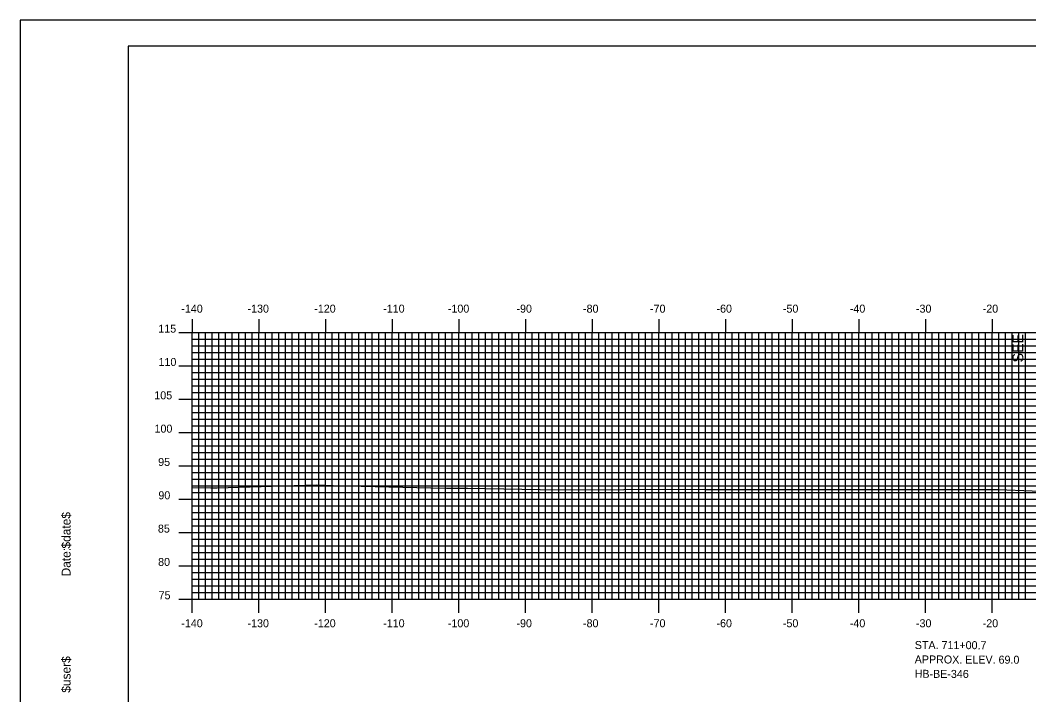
# Model space of a CAD drawing. Extents: x 854903 to 855247, y 364366 to 364586.
# Drawn here: x 854903.5 to 855054.8, y 364484.5 to 364585.7 of the extents above; entities that cross this region are included whole.
import ezdxf

# ---------------------------------------------------------------- set-up
doc = ezdxf.new("R2010")
doc.units = 0
for name, color, linetype in [('ANNOTATION', 7, 'Continuous'), ('BORDER', 7, 'Continuous'), ('BORING - REFUSAL', 7, 'Continuous'), ('H_V ANNOTATION', 7, 'Continuous'), ('MAJOR', 7, 'Continuous'), ('MINOR', 7, 'Continuous'), ('PLOT BOUNDARY', 7, 'Continuous'), ('S_Roadway_Centerline', 7, 'Continuous')]:
    doc.layers.add(name, color=color, linetype=linetype)

msp = doc.modelspace()

# ---------------------------------------------------------------- linework, layer by layer
at = {"layer": 'BORDER'}
msp.add_lwpolyline([(854919.66, 364371.79), (855239.66, 364371.79), (855239.66, 364581.79), (854919.66, 364581.79)], close=True, dxfattribs=at)
at = {"layer": 'MAJOR'}
for p, q in [((854929.26, 364540.79), (854929.26, 364538.79)), ((854939.26, 364540.79), (854939.26, 364538.79)), ((854949.26, 364540.79), (854949.26, 364538.79)), ((854959.26, 364540.79), (854959.26, 364538.79)), ((854969.26, 364540.79), (854969.26, 364538.79)), ((854979.26, 364540.79), (854979.26, 364538.79)), ((854989.26, 364540.79), (854989.26, 364538.79)), ((854999.26, 364540.79), (854999.26, 364538.79)), ((855009.26, 364540.79), (855009.26, 364538.79)), ((855019.26, 364540.79), (855019.26, 364538.79)), ((855029.26, 364540.79), (855029.26, 364538.79)), ((855039.26, 364540.79), (855039.26, 364538.79)), ((855049.26, 364540.79), (855049.26, 364538.79)), ((854927.25, 364538.79), (854929.26, 364538.79)), ((854929.26, 364538.79), (855209.26, 364538.79)), ((854929.26, 364498.79), (854929.26, 364538.79)), ((854929.26, 364498.79), (854929.26, 364538.79)), ((854929.26, 364538.79), (855209.26, 364538.79)), ((854939.26, 364498.79), (854939.26, 364538.79)), ((854949.26, 364498.79), (854949.26, 364538.79)), ((854959.26, 364498.79), (854959.26, 364538.79)), ((854969.26, 364498.79), (854969.26, 364538.79)), ((854979.26, 364498.79), (854979.26, 364538.79)), ((854989.26, 364498.79), (854989.26, 364538.79)), ((854999.26, 364498.79), (854999.26, 364538.79)), ((855009.26, 364498.79), (855009.26, 364538.79)), ((855019.26, 364498.79), (855019.26, 364538.79)), ((855029.26, 364498.79), (855029.26, 364538.79)), ((855039.26, 364498.79), (855039.26, 364538.79)), ((855049.26, 364498.79), (855049.26, 364538.79)), ((854927.25, 364533.79), (854929.26, 364533.79)), ((854929.26, 364533.79), (855209.26, 364533.79)), ((854927.25, 364528.79), (854929.26, 364528.79)), ((854929.26, 364528.79), (855209.26, 364528.79)), ((854927.25, 364523.79), (854929.26, 364523.79)), ((854929.26, 364523.79), (855209.26, 364523.79)), ((854927.25, 364518.79), (854929.26, 364518.79)), ((854929.26, 364518.79), (855209.26, 364518.79)), ((854927.25, 364513.79), (854929.26, 364513.79)), ((854929.26, 364513.79), (855209.26, 364513.79)), ((854927.25, 364508.79), (854929.26, 364508.79)), ((854929.26, 364508.79), (855209.26, 364508.79)), ((854927.25, 364503.79), (854929.26, 364503.79)), ((854929.26, 364503.79), (855209.26, 364503.79)), ((854927.25, 364498.79), (854929.26, 364498.79)), ((854929.26, 364498.79), (855209.26, 364498.79)), ((854929.26, 364498.79), (855209.26, 364498.79)), ((854929.26, 364496.78), (854929.26, 364498.79)), ((854939.26, 364496.78), (854939.26, 364498.79)), ((854949.26, 364496.78), (854949.26, 364498.79)), ((854959.26, 364496.78), (854959.26, 364498.79)), ((854969.26, 364496.78), (854969.26, 364498.79)), ((854979.26, 364496.78), (854979.26, 364498.79)), ((854989.26, 364496.78), (854989.26, 364498.79)), ((854999.26, 364496.78), (854999.26, 364498.79)), ((855009.26, 364496.78), (855009.26, 364498.79)), ((855019.26, 364496.78), (855019.26, 364498.79)), ((855029.26, 364496.78), (855029.26, 364498.79)), ((855039.26, 364496.78), (855039.26, 364498.79)), ((855049.26, 364496.78), (855049.26, 364498.79))]:
    msp.add_line(p, q, dxfattribs=at)
at = {"layer": 'MINOR'}
for p, q in [((854929.26, 364537.79), (855209.26, 364537.79)), ((854929.26, 364537.79), (854931.26, 364537.79)), ((854930.26, 364498.79), (854930.26, 364538.79)), ((854931.26, 364498.79), (854931.26, 364538.79)), ((854932.26, 364498.79), (854932.26, 364538.79)), ((854933.26, 364498.79), (854933.26, 364538.79)), ((854934.26, 364498.79), (854934.26, 364538.79)), ((854935.26, 364498.79), (854935.26, 364538.79)), ((854936.26, 364498.79), (854936.26, 364538.79)), ((854937.26, 364498.79), (854937.26, 364538.79)), ((854938.26, 364498.79), (854938.26, 364538.79)), ((854940.26, 364498.79), (854940.26, 364538.79)), ((854941.26, 364498.79), (854941.26, 364538.79)), ((854942.26, 364498.79), (854942.26, 364538.79)), ((854943.26, 364498.79), (854943.26, 364538.79)), ((854944.26, 364498.79), (854944.26, 364538.79)), ((854945.26, 364498.79), (854945.26, 364538.79)), ((854946.26, 364498.79), (854946.26, 364538.79)), ((854947.26, 364498.79), (854947.26, 364538.79)), ((854948.26, 364498.79), (854948.26, 364538.79)), ((854950.26, 364498.79), (854950.26, 364538.79)), ((854951.26, 364498.79), (854951.26, 364538.79)), ((854952.26, 364498.79), (854952.26, 364538.79)), ((854953.26, 364498.79), (854953.26, 364538.79)), ((854954.26, 364498.79), (854954.26, 364538.79)), ((854955.26, 364498.79), (854955.26, 364538.79)), ((854956.26, 364498.79), (854956.26, 364538.79)), ((854957.26, 364498.79), (854957.26, 364538.79)), ((854958.26, 364498.79), (854958.26, 364538.79)), ((854960.26, 364498.79), (854960.26, 364538.79)), ((854961.26, 364498.79), (854961.26, 364538.79)), ((854962.26, 364498.79), (854962.26, 364538.79)), ((854963.26, 364498.79), (854963.26, 364538.79)), ((854964.26, 364498.79), (854964.26, 364538.79)), ((854965.26, 364498.79), (854965.26, 364538.79)), ((854966.26, 364498.79), (854966.26, 364538.79)), ((854967.26, 364498.79), (854967.26, 364538.79)), ((854968.26, 364498.79), (854968.26, 364538.79)), ((854970.26, 364498.79), (854970.26, 364538.79)), ((854971.26, 364498.79), (854971.26, 364538.79)), ((854972.26, 364498.79), (854972.26, 364538.79)), ((854973.26, 364498.79), (854973.26, 364538.79)), ((854974.26, 364498.79), (854974.26, 364538.79)), ((854975.26, 364498.79), (854975.26, 364538.79)), ((854976.26, 364498.79), (854976.26, 364538.79)), ((854977.26, 364498.79), (854977.26, 364538.79)), ((854978.26, 364498.79), (854978.26, 364538.79)), ((854980.26, 364498.79), (854980.26, 364538.79)), ((854981.26, 364498.79), (854981.26, 364538.79)), ((854982.26, 364498.79), (854982.26, 364538.79)), ((854983.26, 364498.79), (854983.26, 364538.79)), ((854984.26, 364498.79), (854984.26, 364538.79)), ((854985.26, 364498.79), (854985.26, 364538.79)), ((854986.26, 364498.79), (854986.26, 364538.79)), ((854987.26, 364498.79), (854987.26, 364538.79)), ((854988.26, 364498.79), (854988.26, 364538.79)), ((854990.26, 364498.79), (854990.26, 364538.79)), ((854991.26, 364498.79), (854991.26, 364538.79)), ((854992.26, 364498.79), (854992.26, 364538.79)), ((854993.26, 364498.79), (854993.26, 364538.79)), ((854994.26, 364498.79), (854994.26, 364538.79)), ((854995.26, 364498.79), (854995.26, 364538.79)), ((854996.26, 364498.79), (854996.26, 364538.79)), ((854997.26, 364498.79), (854997.26, 364538.79)), ((854998.26, 364498.79), (854998.26, 364538.79)), ((855000.26, 364498.79), (855000.26, 364538.79)), ((855001.26, 364498.79), (855001.26, 364538.79)), ((855002.26, 364498.79), (855002.26, 364538.79)), ((855003.26, 364498.79), (855003.26, 364538.79)), ((855004.26, 364498.79), (855004.26, 364538.79)), ((855005.26, 364498.79), (855005.26, 364538.79)), ((855006.26, 364498.79), (855006.26, 364538.79)), ((855007.26, 364498.79), (855007.26, 364538.79)), ((855008.26, 364498.79), (855008.26, 364538.79)), ((855010.26, 364498.79), (855010.26, 364538.79)), ((855011.26, 364498.79), (855011.26, 364538.79)), ((855012.26, 364498.79), (855012.26, 364538.79)), ((855013.26, 364498.79), (855013.26, 364538.79)), ((855014.26, 364498.79), (855014.26, 364538.79)), ((855015.26, 364498.79), (855015.26, 364538.79)), ((855016.26, 364498.79), (855016.26, 364538.79)), ((855017.26, 364498.79), (855017.26, 364538.79)), ((855018.26, 364498.79), (855018.26, 364538.79)), ((855020.26, 364498.79), (855020.26, 364538.79)), ((855021.26, 364498.79), (855021.26, 364538.79)), ((855022.26, 364498.79), (855022.26, 364538.79)), ((855023.26, 364498.79), (855023.26, 364538.79)), ((855024.26, 364498.79), (855024.26, 364538.79)), ((855025.26, 364498.79), (855025.26, 364538.79)), ((855026.26, 364498.79), (855026.26, 364538.79)), ((855027.26, 364498.79), (855027.26, 364538.79)), ((855028.26, 364498.79), (855028.26, 364538.79)), ((855030.26, 364498.79), (855030.26, 364538.79)), ((855031.26, 364498.79), (855031.26, 364538.79)), ((855032.26, 364498.79), (855032.26, 364538.79)), ((855033.26, 364498.79), (855033.26, 364538.79)), ((855034.26, 364498.79), (855034.26, 364538.79)), ((855035.26, 364498.79), (855035.26, 364538.79)), ((855036.26, 364498.79), (855036.26, 364538.79)), ((855037.26, 364498.79), (855037.26, 364538.79)), ((855038.26, 364498.79), (855038.26, 364538.79)), ((855040.26, 364498.79), (855040.26, 364538.79)), ((855041.26, 364498.79), (855041.26, 364538.79)), ((855042.26, 364498.79), (855042.26, 364538.79)), ((855043.26, 364498.79), (855043.26, 364538.79)), ((855044.26, 364498.79), (855044.26, 364538.79)), ((855045.26, 364498.79), (855045.26, 364538.79)), ((855046.26, 364498.79), (855046.26, 364538.79)), ((855047.26, 364498.79), (855047.26, 364538.79)), ((855048.26, 364498.79), (855048.26, 364538.79)), ((855050.26, 364498.79), (855050.26, 364538.79)), ((855051.26, 364498.79), (855051.26, 364538.79)), ((855052.26, 364498.79), (855052.26, 364538.79)), ((855053.26, 364498.79), (855053.26, 364538.79)), ((855054.26, 364498.79), (855054.26, 364538.79)), ((854929.26, 364536.79), (855209.26, 364536.79)), ((854929.26, 364536.79), (854931.26, 364536.79)), ((854929.26, 364535.79), (855209.26, 364535.79)), ((854929.26, 364535.79), (854931.26, 364535.79)), ((854929.26, 364534.79), (855209.26, 364534.79)), ((854929.26, 364534.79), (854931.26, 364534.79)), ((854929.26, 364532.79), (855209.26, 364532.79)), ((854929.26, 364532.79), (854931.26, 364532.79)), ((854929.26, 364531.79), (855209.26, 364531.79)), ((854929.26, 364531.79), (854931.26, 364531.79)), ((854929.26, 364530.79), (855209.26, 364530.79)), ((854929.26, 364530.79), (854931.26, 364530.79)), ((854929.26, 364529.79), (855209.26, 364529.79)), ((854929.26, 364529.79), (854931.26, 364529.79)), ((854929.26, 364527.79), (855209.26, 364527.79)), ((854929.26, 364527.79), (854931.26, 364527.79)), ((854929.26, 364526.79), (855209.26, 364526.79)), ((854929.26, 364526.79), (854931.26, 364526.79)), ((854929.26, 364525.79), (855209.26, 364525.79)), ((854929.26, 364525.79), (854931.26, 364525.79)), ((854929.26, 364524.79), (855209.26, 364524.79)), ((854929.26, 364524.79), (854931.26, 364524.79)), ((854929.26, 364522.79), (855209.26, 364522.79)), ((854929.26, 364522.79), (854931.26, 364522.79)), ((854929.26, 364521.79), (855209.26, 364521.79)), ((854929.26, 364521.79), (854931.26, 364521.79)), ((854929.26, 364520.79), (855209.26, 364520.79)), ((854929.26, 364520.79), (854931.26, 364520.79)), ((854929.26, 364519.79), (855209.26, 364519.79)), ((854929.26, 364519.79), (854931.26, 364519.79)), ((854929.26, 364517.79), (855209.26, 364517.79)), ((854929.26, 364517.79), (854931.26, 364517.79)), ((854929.26, 364516.79), (855209.26, 364516.79)), ((854929.26, 364516.79), (854931.26, 364516.79)), ((854929.26, 364515.79), (855209.26, 364515.79)), ((854929.26, 364515.79), (854931.26, 364515.79)), ((854929.26, 364514.79), (855209.26, 364514.79)), ((854929.26, 364514.79), (854931.26, 364514.79)), ((854929.26, 364512.79), (855209.26, 364512.79)), ((854929.26, 364512.79), (854931.26, 364512.79)), ((854929.26, 364511.79), (855209.26, 364511.79)), ((854929.26, 364511.79), (854931.26, 364511.79)), ((854929.26, 364510.79), (855209.26, 364510.79)), ((854929.26, 364510.79), (854931.26, 364510.79)), ((854929.26, 364509.79), (855209.26, 364509.79)), ((854929.26, 364509.79), (854931.26, 364509.79)), ((854929.26, 364507.79), (855209.26, 364507.79)), ((854929.26, 364507.79), (854931.26, 364507.79)), ((854929.26, 364506.79), (855209.26, 364506.79)), ((854929.26, 364506.79), (854931.26, 364506.79)), ((854929.26, 364505.79), (855209.26, 364505.79)), ((854929.26, 364505.79), (854931.26, 364505.79)), ((854929.26, 364504.79), (855209.26, 364504.79)), ((854929.26, 364504.79), (854931.26, 364504.79)), ((854929.26, 364502.79), (855209.26, 364502.79)), ((854929.26, 364502.79), (854931.26, 364502.79)), ((854929.26, 364501.79), (855209.26, 364501.79)), ((854929.26, 364501.79), (854931.26, 364501.79)), ((854929.26, 364500.79), (855209.26, 364500.79)), ((854929.26, 364500.79), (854931.26, 364500.79)), ((854929.26, 364499.79), (855209.26, 364499.79)), ((854929.26, 364499.79), (854931.26, 364499.79))]:
    msp.add_line(p, q, dxfattribs=at)
at = {"layer": 'PLOT BOUNDARY'}
msp.add_lwpolyline([(854903.47, 364365.67), (855243.47, 364365.67), (855243.47, 364585.67), (854903.47, 364585.67)], close=True, dxfattribs=at)
at = {"layer": 'S_Roadway_Centerline'}
msp.add_lwpolyline([(854929.26, 364515.56), (854932.08, 364515.49), (854933, 364515.49), (854947.86, 364515.94), (854950.42, 364515.88), (854965.05, 364515.51), (854967.43, 364515.46), (854970.54, 364515.45), (854984.15, 364515.23), (854994.02, 364515.24), (855000.21, 364515.29), (855006.3, 364515.26), (855025.8, 364515.24), (855032.88, 364515.24), (855040.58, 364515.25), (855050.21, 364515.27), (855060.3, 364514.86)], dxfattribs=at)

# ---------------------------------------------------------------- texts
at = {"layer": 'ANNOTATION'}
msp.add_text('SEE', height=1.6, rotation=90, dxfattribs=at).set_placement((855053.92, 364534.31))
at = {"layer": 'BORDER'}
for s, p in [('$date$', (854911.03, 364506.4)), ('Date:', (854911.03, 364502.22)), ('$user$', (854911.03, 364484.77))]:
    msp.add_text(s, height=1.339, rotation=90, dxfattribs=at).set_placement(p)
at = {"layer": 'BORING - REFUSAL'}
for s, p in [('STA. 711+00.7', (855037.65, 364491.33)), ('APPROX. ELEV. 69.0', (855037.64, 364489.17)), ('HB-BE-346', (855037.63, 364487.01))]:
    msp.add_text(s, height=1.2, rotation=359.8142, dxfattribs=at).set_placement(p)
at = {"layer": 'H_V ANNOTATION'}
for s, p in [('-140', (854927.64, 364541.79)), ('-130', (854937.57, 364541.79)), ('-120', (854947.58, 364541.79)), ('-110', (854957.92, 364541.79)), ('-100', (854967.62, 364541.79)), ('-90', (854977.91, 364541.79)), ('-80', (854987.89, 364541.79)), ('-70', (854997.94, 364541.79)), ('-60', (855007.91, 364541.79)), ('-50', (855017.87, 364541.79)), ('-40', (855027.91, 364541.79)), ('-30', (855037.83, 364541.79)), ('-20', (855047.84, 364541.79)), ('115', (854924.19, 364538.79)), ('110', (854924.22, 364533.79)), ('105', (854923.59, 364528.79)), ('100', (854923.62, 364523.79)), ('95', (854924.17, 364518.79)), ('90', (854924.2, 364513.79)), ('85', (854924.13, 364508.79)), ('80', (854924.16, 364503.79)), ('75', (854924.23, 364498.79)), ('-140', (854927.64, 364494.59)), ('-130', (854937.57, 364494.59)), ('-120', (854947.58, 364494.59)), ('-110', (854957.92, 364494.59)), ('-100', (854967.62, 364494.59)), ('-90', (854977.91, 364494.59)), ('-80', (854987.89, 364494.59)), ('-70', (854997.94, 364494.59)), ('-60', (855007.91, 364494.59)), ('-50', (855017.87, 364494.59)), ('-40', (855027.91, 364494.59)), ('-30', (855037.83, 364494.59)), ('-20', (855047.84, 364494.59))]:
    msp.add_text(s, height=1.2, dxfattribs=at).set_placement(p)
at = {"layer": 'MAJOR'}
msp.add_text('-', height=0.012, dxfattribs=at).set_placement((854929.25, 364498.79))

doc.saveas('drawing.dxf')
